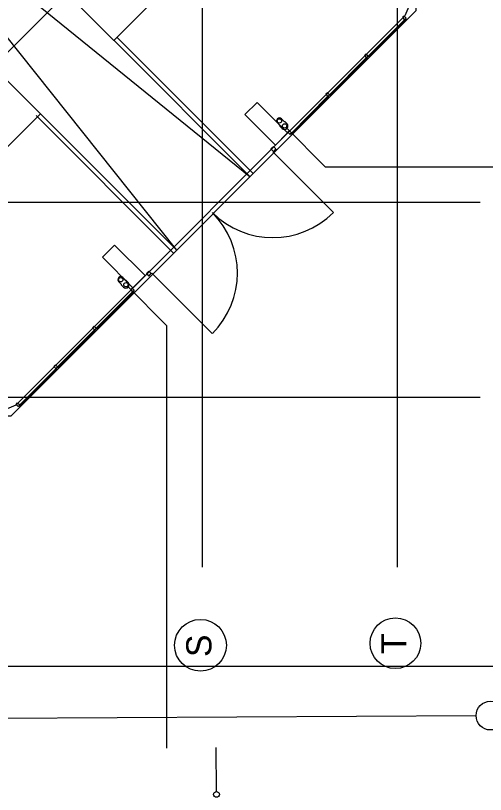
# Model space of a CAD drawing. Extents: x -264031 to -263588, y -1242281 to -1242059.
# Drawn here: x -263808.81 to -263792.47, y -1242254.6 to -1242227.54 of the extents above; entities that cross this region are included whole.
import ezdxf

# ---------------------------------------------------------------- set-up
doc = ezdxf.new("R2010")
doc.units = 0
for name, color, linetype in [('HESCON_OSI_STAVBY_KFA', 7, 'Continuous'), ('KFA_2D_SITUACIA_DSP', 7, 'Continuous'), ('KFA_JESTV_IS_DSP_-_KANAL_SPLASK', 7, 'Continuous')]:
    doc.layers.add(name, color=color, linetype=linetype)

msp = doc.modelspace()

# ---------------------------------------------------------------- linework, layer by layer
at = {"layer": 'HESCON_OSI_STAVBY_KFA'}
for p, q in [((-263802.318, -1242083.237), (-263802.318, -1242246.707)), ((-263795.543, -1242083.237), (-263795.543, -1242246.707)), ((-263792.653, -1242234.032), (-263911.523, -1242234.032)), ((-263792.653, -1242234.032), (-263792.653, -1242234.032)), ((-263792.653, -1242240.807), (-263911.523, -1242240.807)), ((-263792.653, -1242240.807), (-263792.653, -1242240.807))]:
    msp.add_line(p, q, dxfattribs=at)
for centre, radius in [((-263802.378, -1242249.416), 0.899), ((-263795.603, -1242249.345), 0.882)]:
    msp.add_circle(centre, radius, dxfattribs=at)
at = {"layer": 'KFA_2D_SITUACIA_DSP'}
for p, q in [((-263795.043, -1242226.995), (-263795.272, -1242227.55)), ((-263795.272, -1242227.55), (-263808.8, -1242241.078)), ((-263796.558, -1242228.963), (-263795.25, -1242227.654)), ((-263795.232, -1242227.672), (-263796.541, -1242228.98)), ((-263795.297, -1242227.56), (-263795.354, -1242227.617)), ((-263795.354, -1242227.617), (-263795.283, -1242227.688)), ((-263795.227, -1242227.631), (-263795.297, -1242227.56)), ((-263795.283, -1242227.688), (-263795.255, -1242227.659)), ((-263795.255, -1242227.659), (-263795.227, -1242227.631)), ((-263795.25, -1242227.654), (-263795.232, -1242227.672)), ((-263805.283, -1242228.297), (-263800.546, -1242233.035)), ((-263805.389, -1242228.403), (-263800.652, -1242233.141)), ((-263796.59, -1242228.994), (-263797.898, -1242230.303)), ((-263797.881, -1242230.32), (-263796.572, -1242229.012)), ((-263796.617, -1242228.879), (-263796.673, -1242228.936)), ((-263796.673, -1242228.936), (-263796.602, -1242229.007)), ((-263796.546, -1242228.95), (-263796.617, -1242228.879)), ((-263796.602, -1242229.007), (-263796.574, -1242228.978)), ((-263796.572, -1242229.012), (-263796.59, -1242228.994)), ((-263796.574, -1242228.978), (-263796.546, -1242228.95)), ((-263796.541, -1242228.98), (-263796.558, -1242228.963)), ((-263797.961, -1242230.223), (-263798.017, -1242230.28)), ((-263797.89, -1242230.294), (-263797.961, -1242230.223)), ((-263797.934, -1242230.338), (-263799.242, -1242231.647)), ((-263799.225, -1242231.664), (-263797.916, -1242230.356)), ((-263798.017, -1242230.28), (-263797.946, -1242230.351)), ((-263797.946, -1242230.351), (-263797.918, -1242230.322)), ((-263797.916, -1242230.356), (-263797.934, -1242230.338)), ((-263797.918, -1242230.322), (-263797.89, -1242230.294)), ((-263797.898, -1242230.303), (-263797.881, -1242230.32)), ((-263800.834, -1242230.985), (-263800.41, -1242230.561)), ((-263800.41, -1242230.561), (-263799.349, -1242231.622)), ((-263808.093, -1242231.016), (-263803.31, -1242235.799)), ((-263807.987, -1242230.91), (-263803.204, -1242235.693)), ((-263799.774, -1242232.046), (-263800.834, -1242230.985)), ((-263799.705, -1242231.275), (-263799.617, -1242231.364)), ((-263799.559, -1242231.13), (-263799.471, -1242231.218)), ((-263799.471, -1242231.218), (-263799.451, -1242231.218)), ((-263799.373, -1242231.296), (-263799.451, -1242231.218)), ((-263799.451, -1242231.218), (-263799.373, -1242231.296)), ((-263799.617, -1242231.364), (-263799.617, -1242231.383)), ((-263799.617, -1242231.383), (-263799.538, -1242231.462)), ((-263799.402, -1242231.432), (-263798.041, -1242232.793)), ((-263799.28, -1242231.543), (-263799.336, -1242231.599)), ((-263799.209, -1242231.613), (-263799.28, -1242231.543)), ((-263799.349, -1242231.622), (-263799.774, -1242232.046)), ((-263799.336, -1242231.599), (-263799.266, -1242231.67)), ((-263799.266, -1242231.67), (-263799.237, -1242231.642)), ((-263799.242, -1242231.647), (-263799.225, -1242231.664)), ((-263799.237, -1242231.642), (-263799.209, -1242231.613)), ((-263799.929, -1242232.178), (-263799.844, -1242232.093)), ((-263799.844, -1242232.093), (-263799.759, -1242232.178)), ((-263799.844, -1242232.263), (-263799.929, -1242232.178)), ((-263799.844, -1242232.263), (-263799.862, -1242232.281)), ((-263799.862, -1242232.281), (-263797.758, -1242234.384)), ((-263799.759, -1242232.178), (-263799.844, -1242232.263)), ((-263798.041, -1242232.793), (-263790.695, -1242232.793)), ((-263805.365, -1242235.516), (-263805.789, -1242235.94)), ((-263804.304, -1242236.576), (-263805.365, -1242235.516)), ((-263805.789, -1242235.94), (-263804.728, -1242237.001)), ((-263804.172, -1242236.421), (-263804.257, -1242236.506)), ((-263804.087, -1242236.506), (-263804.172, -1242236.421)), ((-263805.075, -1242236.645), (-263804.986, -1242236.733)), ((-263804.728, -1242237.001), (-263804.304, -1242236.576)), ((-263804.257, -1242236.506), (-263804.172, -1242236.591)), ((-263804.172, -1242236.591), (-263804.087, -1242236.506)), ((-263804.087, -1242236.506), (-263804.069, -1242236.488)), ((-263804.069, -1242236.488), (-263801.966, -1242238.592)), ((-263805.22, -1242236.791), (-263805.132, -1242236.879)), ((-263805.132, -1242236.879), (-263805.132, -1242236.899)), ((-263805.132, -1242236.899), (-263805.054, -1242236.977)), ((-263804.986, -1242236.733), (-263804.967, -1242236.733)), ((-263804.888, -1242236.812), (-263804.967, -1242236.733)), ((-263804.967, -1242236.733), (-263804.888, -1242236.812)), ((-263804.918, -1242236.948), (-263803.556, -1242238.308)), ((-263806.012, -1242238.416), (-263804.703, -1242237.108)), ((-263804.686, -1242237.125), (-263805.994, -1242238.434)), ((-263804.807, -1242237.07), (-263804.751, -1242237.014)), ((-263804.737, -1242237.141), (-263804.807, -1242237.07)), ((-263804.751, -1242237.014), (-263804.68, -1242237.084)), ((-263804.708, -1242237.113), (-263804.737, -1242237.141)), ((-263804.68, -1242237.084), (-263804.708, -1242237.113)), ((-263804.703, -1242237.108), (-263804.686, -1242237.125)), ((-263806.127, -1242238.389), (-263806.07, -1242238.333)), ((-263806.07, -1242238.333), (-263805.999, -1242238.404)), ((-263803.556, -1242238.308), (-263803.556, -1242252.989)), ((-263807.356, -1242239.76), (-263806.047, -1242238.452)), ((-263806.03, -1242238.469), (-263807.338, -1242239.778)), ((-263806.056, -1242238.46), (-263806.127, -1242238.389)), ((-263806.028, -1242238.432), (-263806.056, -1242238.46)), ((-263806.047, -1242238.452), (-263806.03, -1242238.469)), ((-263805.999, -1242238.404), (-263806.028, -1242238.432)), ((-263805.994, -1242238.434), (-263806.012, -1242238.416)), ((-263807.471, -1242239.733), (-263807.414, -1242239.677)), ((-263807.414, -1242239.677), (-263807.343, -1242239.748)), ((-263807.387, -1242239.792), (-263808.696, -1242241.1)), ((-263808.678, -1242241.118), (-263807.37, -1242239.809)), ((-263807.4, -1242239.804), (-263807.471, -1242239.733)), ((-263807.372, -1242239.776), (-263807.4, -1242239.804)), ((-263807.37, -1242239.809), (-263807.387, -1242239.792)), ((-263807.343, -1242239.748), (-263807.372, -1242239.776)), ((-263807.338, -1242239.778), (-263807.356, -1242239.76)), ((-263808.79, -1242241.053), (-263808.733, -1242240.996)), ((-263808.733, -1242240.996), (-263808.662, -1242241.067)), ((-263808.8, -1242241.078), (-263809.355, -1242241.307)), ((-263808.719, -1242241.123), (-263808.79, -1242241.053)), ((-263808.691, -1242241.095), (-263808.719, -1242241.123)), ((-263808.696, -1242241.1), (-263808.678, -1242241.118)), ((-263808.662, -1242241.067), (-263808.691, -1242241.095)), ((-263924.143, -1242250.14), (-263788.143, -1242250.14)), ((-263801.822, -1242254.497), (-263801.837, -1242252.972))]:
    msp.add_line(p, q, dxfattribs=at)
for points in [[(-263794.893, -1242227.382), (-263808.968, -1242241.457), (-263894.968, -1242241.457), (-263909.043, -1242227.382), (-263909.043, -1242196.333), (-263914.143, -1242196.333), (-263914.143, -1242132.433), (-263909.043, -1242132.433), (-263909.043, -1242101.382), (-263894.968, -1242087.307), (-263808.968, -1242087.307), (-263794.893, -1242101.382), (-263794.893, -1242227.382)], [(-263909.043, -1242125.432), (-263902.343, -1242125.432), (-263902.343, -1242104.482), (-263902.112, -1242103.927), (-263898.54, -1242100.355), (-263895.995, -1242097.81), (-263892.423, -1242094.238), (-263891.868, -1242094.007), (-263812.071, -1242094.007), (-263811.513, -1242094.238), (-263801.823, -1242103.927), (-263801.593, -1242104.482), (-263801.593, -1242224.282), (-263801.824, -1242224.838), (-263805.392, -1242228.407)], [(-263811.918, -1242108.434), (-263811.918, -1242220.33), (-263812.262, -1242220.675), (-263809.862, -1242221.669), (-263810.999, -1242222.806), (-263807.039, -1242226.765), (-263809.585, -1242229.311), (-263813.545, -1242225.351), (-263814.681, -1242226.488), (-263815.675, -1242224.088), (-263816.02, -1242224.432), (-263887.916, -1242224.432)], [(-263807.941, -1242230.956), (-263813.544, -1242225.352), (-263814.681, -1242226.488), (-263815.675, -1242224.088), (-263812.262, -1242220.675)], [(-263812.262, -1242220.675), (-263809.863, -1242221.669), (-263810.999, -1242222.806), (-263805.392, -1242228.407)], [(-263803.204, -1242235.693), (-263813.559, -1242222.704), (-263800.652, -1242233.141)], [(-263807.942, -1242230.956), (-263811.512, -1242234.526), (-263812.068, -1242234.757), (-263891.868, -1242234.757), (-263892.424, -1242234.526), (-263895.994, -1242230.956)]]:
    msp.add_lwpolyline(points, dxfattribs=at)
for centre, radius in [((-263799.632, -1242231.202), 0.075), ((-263799.455, -1242231.379), 0.075), ((-263805.148, -1242236.718), 0.075), ((-263804.971, -1242236.895), 0.075), ((-263801.821, -1242254.597), 0.1)]:
    msp.add_circle(centre, radius, dxfattribs=at)
for centre, radius, start, end in [((-263799.632, -1242231.202), 0.103, 45, 225), ((-263799.455, -1242231.379), 0.117, 225, 45), ((-263804.069, -1242236.488), 2.975, 315.0001, 45.0001), ((-263799.862, -1242232.281), 2.975, 224.9999, 314.9999), ((-263805.148, -1242236.718), 0.103, 45, 225), ((-263804.971, -1242236.895), 0.117, 225, 45)]:
    msp.add_arc(centre, radius, start, end, dxfattribs=at)
at = {"layer": 'KFA_JESTV_IS_DSP_-_KANAL_SPLASK'}
msp.add_line((-263792.798, -1242251.862), (-263831.703, -1242252.086), dxfattribs=at)
msp.add_circle((-263792.298, -1242251.859), 0.5, dxfattribs=at)

# ---------------------------------------------------------------- texts
at = {"layer": 'HESCON_OSI_STAVBY_KFA'}
for s, p in [('S', (-263801.997, -1242249.824)), ('T', (-263795.222, -1242249.718))]:
    msp.add_text(s, height=0.875, rotation=90, dxfattribs=at).set_placement(p)

doc.saveas('drawing.dxf')
